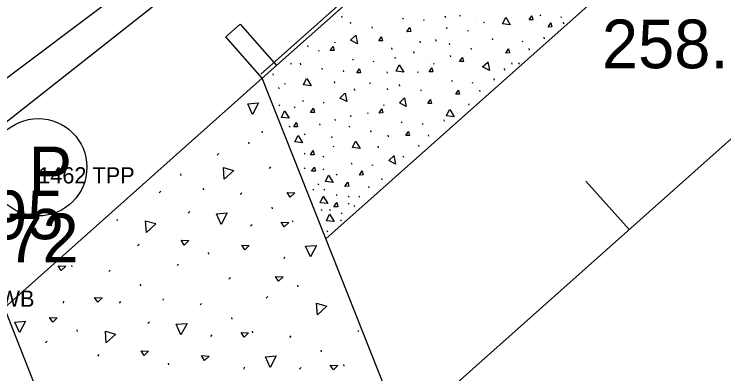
# Model space of a CAD drawing. Extents: x 49683 to 58852, y 49525 to 54803.
# Drawn here: x 55371.73 to 55415.49, y 53160.72 to 53182.88 of the extents above; entities that cross this region are included whole.
import ezdxf

# ---------------------------------------------------------------- set-up
doc = ezdxf.new("R2010")
doc.units = 0
for name, color, linetype in [('Level 15', 7, 'Continuous'), ('Level 19', 7, 'Continuous'), ('Level 20', 7, 'Continuous'), ('Level 27', 7, 'Continuous'), ('Level 3', 7, 'Continuous'), ('Level 32', 7, 'Continuous'), ('Level 55', 7, 'Continuous'), ('Level 59', 7, 'Continuous'), ('Level 7', 7, 'Continuous'), ('Level 8', 7, 'Continuous'), ('Level 9', 7, 'Continuous')]:
    doc.layers.add(name, color=color, linetype=linetype)

# ---------------------------------------------------------------- blocks, each defined once
blk = doc.blocks.new('TPP')
at = {"layer": 'Level 9'}
blk.add_circle((0, 0), 3, dxfattribs=at)
blk.add_text('P', height=3, dxfattribs=at).set_placement((-0.589, -1.729))

msp = doc.modelspace()

# ---------------------------------------------------------------- linework, layer by layer
at = {"layer": 'Level 15'}
for p, q in [((55414.815, 53190.25), (55390.953, 53169.04)), ((55398.961, 53189.537), (55387.03, 53178.933)), ((55371.123, 53164.793), (55387.03, 53178.933)), ((55404.292, 53135.407), (55387.03, 53178.933)), ((55387.037, 53175.577), (55387.013, 53175.674)), ((55386.216, 53174.896), (55386.193, 53174.993)), ((55384.343, 53174.293), (55384.248, 53174.194)), ((55387.542, 53173.468), (55387.448, 53173.37)), ((55382.018, 53172.945), (55381.994, 53173.043)), ((55380.763, 53171.978), (55380.668, 53171.88)), ((55383.419, 53172.06), (55383.395, 53172.157)), ((55385.765, 53171.871), (55385.67, 53171.772)), ((55387.656, 53170.893), (55387.632, 53170.991)), ((55382.55, 53170.723), (55382.455, 53170.624)), ((55378.101, 53170.142), (55378.077, 53170.239)), ((55388.922, 53170.057), (55388.899, 53170.154)), ((55386.401, 53169.926), (55386.306, 53169.828)), ((55379.427, 53168.714), (55379.332, 53168.616)), ((55383.739, 53168.09), (55383.715, 53168.187)), ((55388.38, 53167.817), (55388.41, 53167.939)), ((55381.866, 53167.487), (55381.771, 53167.388)), ((55375.303, 53167.306), (55375.28, 53167.403)), ((55377.65, 53167.117), (55377.555, 53167.019)), ((55385.065, 53166.662), (55384.97, 53166.564)), ((55379.541, 53166.14), (55379.517, 53166.237)), ((55389.243, 53166.086), (55389.219, 53166.184)), ((55380.941, 53165.254), (55380.918, 53165.351)), ((55387.37, 53165.484), (55387.275, 53165.385)), ((55374.761, 53165.067), (55374.791, 53165.189)), ((55378.286, 53165.173), (55378.191, 53165.074)), ((55383.288, 53165.065), (55383.193, 53164.966)), ((55388.385, 53121.267), (55371.123, 53164.793)), ((55385.179, 53164.087), (55385.155, 53164.185)), ((55380.073, 53163.917), (55379.978, 53163.818)), ((55375.624, 53163.336), (55375.6, 53163.433)), ((55383.924, 53163.121), (55383.829, 53163.022)), ((55386.445, 53163.251), (55386.422, 53163.348)), ((55388.792, 53163.061), (55388.697, 53162.963)), ((55392.966, 53163.388), (55392.913, 53163.333)), ((55373.751, 53162.733), (55373.656, 53162.635)), ((55390.683, 53162.084), (55390.659, 53162.181)), ((55376.95, 53161.908), (55376.855, 53161.81)), ((55381.262, 53161.284), (55381.238, 53161.381)), ((55392.084, 53161.199), (55392.06, 53161.296)), ((55385.903, 53161.011), (55385.933, 53161.133)), ((55389.428, 53161.117), (55389.333, 53161.019))]:
    msp.add_line(p, q, dxfattribs=at)
for points in [[(55386.792, 53177.416), (55386.417, 53176.708), (55386.126, 53177.36), (55386.778, 53177.416)], [(55385.275, 53173.248), (55384.681, 53172.711), (55384.63, 53173.424), (55385.262, 53173.253)], [(55389.03, 53171.87), (55388.755, 53171.601), (55388.566, 53171.892), (55389.03, 53171.87)], [(55384.864, 53170.639), (55384.489, 53169.931), (55384.198, 53170.583), (55384.85, 53170.639)], [(55380.472, 53169.971), (55379.878, 53169.434), (55379.827, 53170.147), (55380.459, 53169.976)], [(55388.661, 53170.049), (55388.385, 53169.78), (55388.196, 53170.07), (55388.661, 53170.049)], [(55382.494, 53168.927), (55382.219, 53168.658), (55382.029, 53168.948), (55382.494, 53168.927)], [(55386.22, 53168.626), (55385.945, 53168.357), (55385.756, 53168.647), (55386.22, 53168.626)], [(55390.368, 53168.635), (55389.993, 53167.928), (55389.702, 53168.58), (55390.354, 53168.635)], [(55374.907, 53167.347), (55374.632, 53167.078), (55374.442, 53167.369), (55374.907, 53167.347)], [(55388.309, 53166.698), (55388.034, 53166.429), (55387.844, 53166.719), (55388.309, 53166.698)], [(55377.153, 53165.404), (55376.878, 53165.135), (55376.689, 53165.425), (55377.153, 53165.404)], [(55391.017, 53164.894), (55390.423, 53164.358), (55390.372, 53165.07), (55391.004, 53164.899)], [(55372.422, 53163.969), (55372.048, 53163.261), (55371.756, 53163.913), (55372.409, 53163.969)], [(55374.378, 53164.173), (55374.103, 53163.904), (55373.914, 53164.195), (55374.378, 53164.173)], [(55382.387, 53163.833), (55382.012, 53163.125), (55381.721, 53163.777), (55382.373, 53163.833)], [(55377.995, 53163.165), (55377.401, 53162.629), (55377.35, 53163.341), (55377.982, 53163.17)], [(55386.183, 53163.243), (55385.908, 53162.974), (55385.719, 53163.265), (55386.183, 53163.243)], [(55380.016, 53162.121), (55379.741, 53161.852), (55379.552, 53162.143), (55380.016, 53162.121)], [(55383.743, 53161.82), (55383.468, 53161.551), (55383.279, 53161.842), (55383.743, 53161.82)], [(55387.891, 53161.829), (55387.516, 53161.122), (55387.225, 53161.774), (55387.877, 53161.829)], [(55391.687, 53161.24), (55391.412, 53160.971), (55391.223, 53161.261), (55391.687, 53161.24)]]:
    msp.add_lwpolyline(points, dxfattribs=at)
at = {"layer": 'Level 19'}
for p, q in [((54181.768, 52078.16), (56150.851, 53828.445)), ((55409.65, 53169.604), (55406.993, 53172.594))]:
    msp.add_line(p, q, dxfattribs=at)
at = {"layer": 'Level 20'}
msp.add_line((55390.953, 53169.04), (56142.879, 53837.415), dxfattribs=at)
at = {"layer": 'Level 27'}
for p, q in [((55386.932, 53179.18), (55428.906, 53216.49)), ((55387.03, 53178.933), (55429.072, 53216.303)), ((55384.772, 53181.474), (55385.655, 53182.259)), ((55385.655, 53182.259), (55387.914, 53179.718)), ((55387.03, 53178.933), (55384.772, 53181.474)), ((55387.914, 53179.718), (55387.03, 53178.933))]:
    msp.add_line(p, q, dxfattribs=at)
at = {"layer": 'Level 3'}
msp.add_line((55362.189, 53172.14), (55389.472, 53192.624), dxfattribs=at)
at = {"layer": 'Level 7'}
msp.add_line((55421.996, 53216.165), (55364.505, 53170.939), dxfattribs=at)
at = {"layer": 'Level 8'}
for p, q in [((55391.912, 53182.763), (55391.936, 53182.675)), ((55398.295, 53182.767), (55398.319, 53182.679)), ((55399.2, 53182.834), (55399.224, 53182.746)), ((55404.214, 53182.767), (55404.154, 53182.825)), ((55392.453, 53182.394), (55392.477, 53182.306)), ((55395.74, 53182.581), (55395.68, 53182.639)), ((55397.026, 53182.49), (55396.962, 53182.509)), ((55400.173, 53182.553), (55400.173, 53182.553)), ((55400.302, 53182.659), (55400.302, 53182.659)), ((55400.738, 53182.336), (55400.674, 53182.356)), ((55404.366, 53182.396), (55404.366, 53182.396)), ((55405.5, 53182.675), (55405.436, 53182.695)), ((55405.575, 53182.377), (55405.599, 53182.289)), ((55393.784, 53182.1), (55393.809, 53182.012)), ((55398.391, 53182.056), (55398.415, 53181.968)), ((55391.112, 53181.433), (55391.112, 53181.433)), ((55399.755, 53181.832), (55399.691, 53181.852)), ((55404.395, 53181.452), (55404.419, 53181.364)), ((55390.983, 53181.327), (55390.983, 53181.327)), ((55391.549, 53181.111), (55391.485, 53181.13)), ((55396.737, 53181.21), (55396.761, 53181.122)), ((55397.711, 53181.311), (55397.735, 53181.223)), ((55398.553, 53181.078), (55398.577, 53180.99)), ((55401.211, 53181.384), (55401.236, 53181.297)), ((55403.126, 53181.174), (55403.062, 53181.194)), ((55389.808, 53180.948), (55389.832, 53180.86)), ((55390.565, 53180.607), (55390.502, 53180.626)), ((55394.992, 53180.798), (55395.016, 53180.71)), ((55396.352, 53180.571), (55396.376, 53180.483)), ((55399.885, 53180.784), (55399.909, 53180.696)), ((55403.47, 53180.757), (55403.495, 53180.669)), ((55395.205, 53180.226), (55395.23, 53180.138)), ((55397.212, 53180.118), (55397.212, 53180.118)), ((55398.617, 53180.339), (55398.642, 53180.251)), ((55388.776, 53179.885), (55388.8, 53179.797)), ((55389.363, 53179.853), (55389.388, 53179.765)), ((55392.65, 53180.04), (55392.59, 53180.099)), ((55393.936, 53179.949), (55393.872, 53179.968)), ((55397.084, 53180.012), (55397.084, 53180.012)), ((55397.649, 53179.795), (55397.585, 53179.815)), ((55402.402, 53179.882), (55402.426, 53179.794)), ((55402.837, 53179.895), (55402.861, 53179.807)), ((55390.695, 53179.559), (55390.719, 53179.471)), ((55392.014, 53179.405), (55392.038, 53179.317)), ((55394.7, 53179.334), (55394.724, 53179.246)), ((55396.666, 53179.292), (55396.602, 53179.311)), ((55401.949, 53179.525), (55401.973, 53179.437)), ((55387.675, 53179.205), (55387.699, 53179.117)), ((55401.306, 53178.911), (55401.33, 53178.823)), ((55388.459, 53178.57), (55388.395, 53178.589)), ((55391.463, 53178.724), (55391.488, 53178.636)), ((55393.647, 53178.669), (55393.672, 53178.581)), ((55395.463, 53178.537), (55395.488, 53178.45)), ((55398.751, 53178.725), (55398.69, 53178.783)), ((55400.036, 53178.633), (55399.973, 53178.653)), ((55388.031, 53178.362), (55388.056, 53178.274)), ((55392.693, 53178.27), (55392.718, 53178.182)), ((55394.732, 53178.297), (55394.757, 53178.209)), ((55396.795, 53178.243), (55396.819, 53178.155)), ((55400.431, 53178.206), (55400.455, 53178.118)), ((55389.561, 53177.499), (55389.501, 53177.558)), ((55394.123, 53177.577), (55394.123, 53177.577)), ((55388.102, 53177.242), (55388.042, 53177.301)), ((55389.002, 53177.196), (55389.027, 53177.108)), ((55390.847, 53177.408), (55390.783, 53177.427)), ((55393.994, 53177.471), (55393.994, 53177.471)), ((55394.559, 53177.255), (55394.495, 53177.274)), ((55399.747, 53177.354), (55399.772, 53177.266)), ((55392.466, 53176.645), (55392.491, 53176.557)), ((55393.576, 53176.751), (55393.512, 53176.77)), ((55391.495, 53176.418), (55391.519, 53176.33)), ((55395.661, 53176.184), (55395.601, 53176.243)), ((55398.216, 53176.37), (55398.24, 53176.282)), ((55388.741, 53175.923), (55388.681, 53175.981)), ((55390.558, 53176.129), (55390.582, 53176.041)), ((55392.374, 53175.997), (55392.398, 53175.909)), ((55396.947, 53176.093), (55396.883, 53176.112)), ((55389.672, 53175.438), (55389.612, 53175.496)), ((55391.301, 53175.349), (55391.325, 53175.261)), ((55393.706, 53175.703), (55393.73, 53175.615)), ((55394.765, 53175.419), (55394.79, 53175.331)), ((55397.258, 53175.451), (55397.282, 53175.363)), ((55391.47, 53174.714), (55391.406, 53174.733)), ((55394.15, 53174.738), (55394.175, 53174.65)), ((55396.658, 53174.813), (55396.682, 53174.725)), ((55389.672, 53174.254), (55389.612, 53174.312)), ((55390.816, 53174.079), (55390.756, 53174.138)), ((55395.704, 53174.155), (55395.728, 53174.067)), ((55392.572, 53173.643), (55392.512, 53173.702)), ((55393.858, 53173.552), (55393.794, 53173.571)), ((55389.672, 53173.361), (55389.612, 53173.42)), ((55390.816, 53173.284), (55390.756, 53173.342)), ((55391.65, 53172.954), (55391.59, 53173.012)), ((55394.377, 53172.762), (55394.401, 53172.674)), ((55390.506, 53172.372), (55390.446, 53172.43)), ((55393.569, 53172.272), (55393.593, 53172.184)), ((55390.215, 53172.042), (55390.155, 53172.1)), ((55390.894, 53172.042), (55390.834, 53172.1)), ((55391.65, 53171.712), (55391.59, 53171.77)), ((55392.387, 53171.615), (55392.327, 53171.673)), ((55393.046, 53171.615), (55392.986, 53171.673)), ((55392.387, 53171.169), (55392.327, 53171.227)), ((55392.736, 53171.033), (55392.676, 53171.091)), ((55390.719, 53170.78), (55390.659, 53170.839)), ((55391.243, 53170.78), (55391.183, 53170.839)), ((55391.96, 53170.586), (55391.9, 53170.645)), ((55391.921, 53170.14), (55391.861, 53170.199)), ((55391.068, 53169.461), (55391.008, 53169.519))]:
    msp.add_line(p, q, dxfattribs=at)
for points in [[(55403.659, 53182.78), (55403.72, 53182.531), (55403.489, 53182.521), (55403.659, 53182.78)], [(55402.044, 53182.684), (55402.323, 53182.229), (55401.85, 53182.283), (55402.039, 53182.676)], [(55404.832, 53182.346), (55404.893, 53182.097), (55404.662, 53182.087), (55404.832, 53182.346)], [(55396.123, 53182.058), (55396.184, 53181.809), (55395.953, 53181.799), (55396.123, 53182.058)], [(55392.791, 53181.577), (55392.897, 53181.055), (55392.471, 53181.267), (55392.784, 53181.572)], [(55394.388, 53181.488), (55394.449, 53181.239), (55394.218, 53181.228), (55394.388, 53181.488)], [(55391.391, 53180.897), (55391.452, 53180.648), (55391.221, 53180.638), (55391.391, 53180.897)], [(55402.223, 53180.743), (55402.284, 53180.494), (55402.053, 53180.484), (55402.223, 53180.743)], [(55399.368, 53180.212), (55399.429, 53179.963), (55399.198, 53179.953), (55399.368, 53180.212)], [(55395.48, 53179.765), (55395.759, 53179.31), (55395.286, 53179.364), (55395.475, 53179.757)], [(55400.938, 53179.937), (55401.045, 53179.414), (55400.619, 53179.626), (55400.931, 53179.931)], [(55393.033, 53179.518), (55393.095, 53179.269), (55392.864, 53179.258), (55393.033, 53179.518)], [(55397.491, 53179.582), (55397.552, 53179.333), (55397.321, 53179.322), (55397.491, 53179.582)], [(55389.765, 53178.918), (55390.044, 53178.463), (55389.571, 53178.517), (55389.76, 53178.91)], [(55392.132, 53178.022), (55392.239, 53177.499), (55391.813, 53177.712), (55392.125, 53178.016)], [(55399.134, 53178.202), (55399.195, 53177.953), (55398.964, 53177.943), (55399.134, 53178.202)], [(55395.802, 53177.721), (55395.908, 53177.198), (55395.482, 53177.411), (55395.794, 53177.715)], [(55397.399, 53177.632), (55397.46, 53177.383), (55397.229, 53177.372), (55397.399, 53177.632)], [(55390.179, 53177.079), (55390.24, 53176.83), (55390.009, 53176.82), (55390.179, 53177.079)], [(55388.404, 53176.923), (55388.683, 53176.468), (55388.21, 53176.522), (55388.399, 53176.915)], [(55394.401, 53177.041), (55394.463, 53176.792), (55394.231, 53176.782), (55394.401, 53177.041)], [(55398.588, 53177.01), (55398.867, 53176.555), (55398.394, 53176.609), (55398.583, 53177.002)], [(55389.135, 53176.198), (55389.196, 53175.948), (55388.965, 53175.938), (55389.135, 53176.198)], [(55389.238, 53175.41), (55389.517, 53174.955), (55389.044, 53175.008), (55389.233, 53175.402)], [(55396.044, 53175.661), (55396.105, 53175.412), (55395.874, 53175.402), (55396.044, 53175.661)], [(55392.776, 53175.062), (55393.055, 53174.607), (55392.582, 53174.661), (55392.771, 53175.054)], [(55390.162, 53174.471), (55390.223, 53174.221), (55389.992, 53174.211), (55390.162, 53174.471)], [(55395.143, 53174.166), (55395.25, 53173.643), (55394.824, 53173.856), (55395.136, 53174.16)], [(55390.24, 53173.461), (55390.301, 53173.212), (55390.07, 53173.202), (55390.24, 53173.461)], [(55393.19, 53173.223), (55393.251, 53172.974), (55393.02, 53172.963), (55393.19, 53173.223)], [(55391.119, 53172.965), (55391.398, 53172.51), (55390.925, 53172.563), (55391.114, 53172.957)], [(55392.295, 53172.53), (55392.356, 53172.281), (55392.125, 53172.271), (55392.295, 53172.53)], [(55390.789, 53171.664), (55391.068, 53171.209), (55390.595, 53171.263), (55390.784, 53171.656)], [(55391.617, 53171.269), (55391.678, 53171.02), (55391.447, 53171.009), (55391.617, 53171.269)], [(55391.177, 53170.558), (55391.456, 53170.103), (55390.983, 53170.157), (55391.172, 53170.55)]]:
    msp.add_lwpolyline(points, dxfattribs=at)

# ---------------------------------------------------------------- block references
at = {"layer": 'Level 9'}
msp.add_blockref('TPP', (55373.209, 53173.449), dxfattribs=at)

# ---------------------------------------------------------------- texts
at = {"layer": 'Level 32'}
for s, p in [('258.82', (55407.974, 53179.547)), ('267.95', (55362.498, 53169.013)), ('267.72', (55363.433, 53167.593))]:
    msp.add_text(s, height=3, dxfattribs=at).set_placement(p)
at = {"layer": 'Level 55'}
msp.add_text('1663 WWB', height=1, dxfattribs=at).set_placement((55366.216, 53164.853))
at = {"layer": 'Level 59'}
msp.add_text('1462 TPP', height=1, dxfattribs=at).set_placement((55373.209, 53172.449))

doc.saveas('drawing.dxf')
